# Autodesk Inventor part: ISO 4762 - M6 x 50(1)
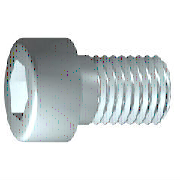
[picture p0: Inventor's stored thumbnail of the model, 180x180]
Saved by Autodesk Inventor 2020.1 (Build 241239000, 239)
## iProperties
Created: 2019-01
Part Number: ISO 4762 - M6 x 50(1)
Material: Edelstahl, 440C
Description: Innensechskantschraube
Document SubType Name: Modeling
Standard: ISO 4762
Designer: lutzd
Standard Revision: Fourth edition 2004-03-01
Standards Organization: ISO
Language: de-DE
Size Designation: M6 x 50
Categories: <MemberInstance><Categories><Category DisplayName="Verbindungselemente" InternalName="e4da775c-781d-43d5-af7c-5136215cf5a6" Mnemonic="FSTN"><Category DisplayNam
Mass: 13.9518 g
Surface Area: 13.2959 cm^2
Volume: 1.80023 cm^3
Density: 7.75 g/cm^3
Appearance: Halbpoliert
IsCustomPart: 0
Author: lutzd
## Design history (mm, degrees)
body "Solid1"
sketch "Skizze1"
  geometry: L1 (-1.333, 0)-(50, 0); L2 (50, 0)-(50, 3); L3 (50, 3)-(26, 3); L4 (26, 3)-(25.386, 3); L5 (25.386, 3)-(0, 3); L6 (0, 3)-(0, 5); L7 (0, 5)-(-6, 5); L8 (-6, 5)-(-6, 2.887); L9 (-6, 2.887)-(-3, 2.887); L10 (-3, 2.887)-(-1.333, 0); L11 (-17.2, 0)-(61.2, 0) reference; L12 (0, -1)-(0, 6) reference; L13 (26, 3)-(0, 3)
  constraints: 22 end point, 6 parallel, 2 collinear, 2 perpendicular, 1 horizontal, 1 point on line
  dimensions: "d1" = 24 distance from line of L3.end L2 (= GEL); "d2" = 0.61355 distance of L4.end L3.end (computed from GAL); "d3" = 6 distance between parallel lines of L8 L6 (= KOH); "d4" = 3 distance of L8.end L9.end (= INTI); "d5" = 60 deg angle of L10 L1; "d6" = 6 diameter of L3 L1 (= GD); "d7" = 6 diameter of L5 L1 (= BDM); "d8" = 5.7735 diameter of L9 L1 (= 1.1547 x SW); "d9" = 10 diameter of L7 L1 (= KOD); "d26" = 50 distance between parallel lines of L12 L2 (= NLG)
workplane "Work Plane1"
fillet "Fillet2" dims "d30" = 0.1 (= R)
revolve "Körper" stored, may be unused: angle "d10" = 90 deg
sketch "Skizze2"
  geometry: L1 (0, -7)-(0, 7) reference; L2 (-7, 0)-(7, 0) reference; L3 (2.887, 0)-(1.443, -2.5); L4 (1.443, -2.5)-(-1.443, -2.5); L5 (-1.443, -2.5)-(-2.887, 0); L6 (-2.887, 0)-(-1.443, 2.5); L7 (-1.443, 2.5)-(1.443, 2.5); L8 (1.443, 2.5)-(2.887, 0); 2 further points
  constraints: 12 end point, 1 coincident, 1 horizontal alignment, 1 point on line, 12 other
extrude "Loch" join sketch "Skizze2" stored distance "d11" = 10; taper "d12" = 0 deg
fillet "Rundung1" dims "d17" = 0.6 (= RR)
feature "Gewinde" dims "d13" = 24 (= GEL), "d14" = 0
chamfer "Fase1" distance "d15" = 0.61345 (= -0.5 x SPD + 0.5 x GD); stored, may be unused: second distance "d16" = 0.61345 (= GUL), angle "d27" = 45 deg
other parameters: "GD" = 6 [user parameter; used in 2 equation terms], "NLG" = 50 [user parameter; used in 1 equation term], "GEL" = 24 [user parameter; used in 2 equation terms], "KOD" = 10 [user parameter; used in 1 equation term], "KOH" = 6 [user parameter; used in 1 equation term], "INTI" = 3 [user parameter; used in 1 equation term], "GAL" = 0.61345 (= 0.61345 x PTC) [user parameter; used in 1 equation term], "GUL" = 0.61345 (= 0.61345 x PTC) [user parameter; used in 1 equation term], "BDM" = 6 (= NND) [user parameter; used in 1 equation term], "SW" = 5 [user parameter; used in 2 equation terms], "RR" = 0.6 [user parameter; used in 1 equation term], "SPD" = 4.7731 (= NND - 1.2269 x PTC) [user parameter; used in 1 equation term], "d19" = 0, "d28" = 0, "d29" = 0, "R" = 0.1 [user parameter; used in 1 equation term], "TOA" = 30 deg [user parameter], "GD1" = 4.7731 (= THREADDIA - 1.2269 x PTC) [user parameter], "THREADDIA" = 6 [user parameter; used in 1 equation term], "FAWI" = 45 deg [user parameter], "PTC" = 1 [user parameter; used in 5 equation terms], "NND" = 6 [user parameter; used in 2 equation terms], "E0" = 5.775 (= 1.155 x SW) [user parameter]
